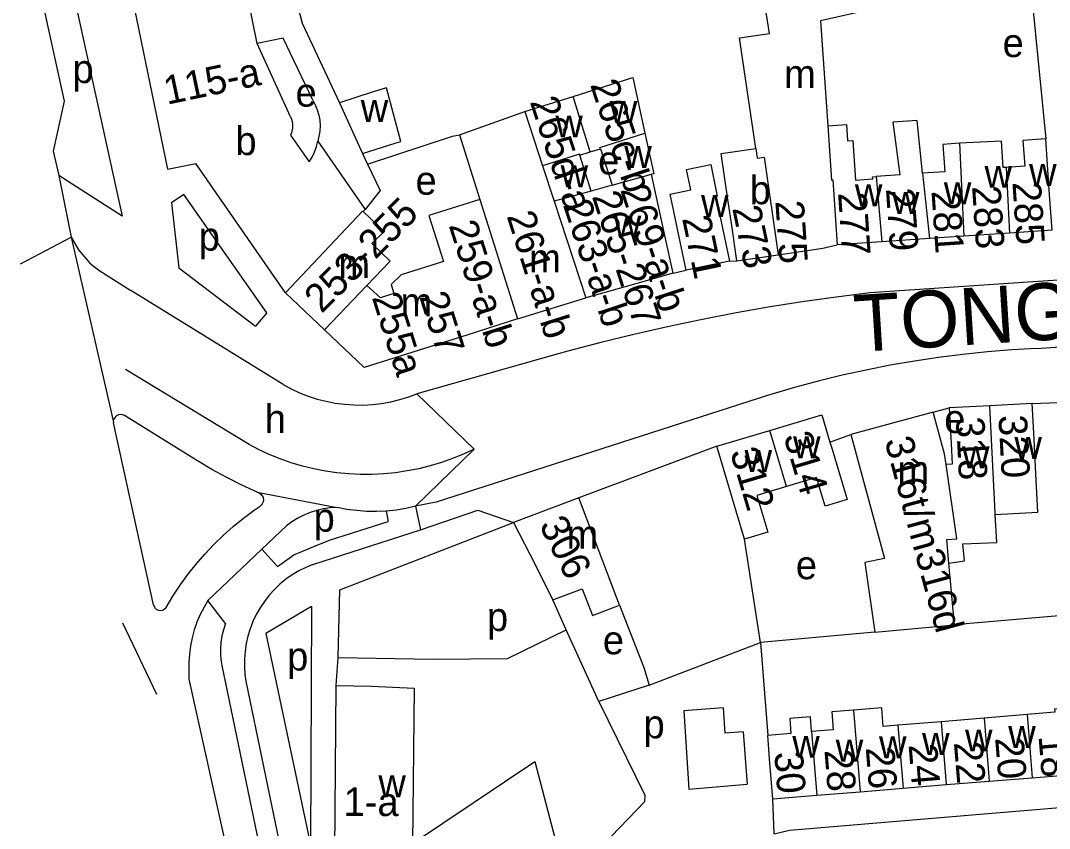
# Model space of a CAD drawing. Extents: x 163012 to 165277, y 382513 to 383987.
# Drawn here: x 163122.8 to 163267.3, y 383543.8 to 383657.3 of the extents above; entities that cross this region are included whole.
import ezdxf

# ---------------------------------------------------------------- set-up
doc = ezdxf.new("R2010")
doc.units = 0
for name, color, linetype in [('BLT_Basislijn', 7, 'Continuous'), ('BLT_Bebouwing', 7, 'Continuous'), ('BLT_Centroide', 7, 'Continuous'), ('BLT_Huisnummer', 7, 'Continuous'), ('BLT_Huisnummer_ tussenligend', 7, 'Continuous'), ('BLT_Huisnummer_reeks', 7, 'Continuous'), ('BLT_Onderverdeling_panden', 7, 'Continuous'), ('BLT_Straatnaam_hoofdweg', 7, 'Continuous'), ('BLT_Vlakafsluiter', 7, 'Continuous')]:
    doc.layers.add(name, color=color, linetype=linetype)

msp = doc.modelspace()

# ---------------------------------------------------------------- linework, layer by layer
at = {"layer": 'BLT_Basislijn'}
for p, q in [((163129.23, 383665.51), (163137.03, 383629.85)), ((163264.55, 383663.73), (163266.82, 383640.7)), ((163170.79, 383638.64), (163171.51, 383637.16)), ((163128.13, 383635.56), (163129.89, 383626.91)), ((163137.03, 383629.85), (163128.13, 383635.56)), ((163145.71, 383632.87), (163143.96, 383631.72)), ((163143.96, 383631.72), (163144.99, 383622.58)), ((163157.35, 383616.28), (163145.71, 383632.87)), ((163222.36, 383623.51), (163223.43, 383623.57)), ((163144.99, 383622.58), (163155.75, 383614.4)), ((163214.46, 383621.84), (163216.29, 383622.24)), ((163292.17, 383622.44), (163242.12, 383619.08)), ((163159.64, 383606.21), (163138.24, 383619.41)), ((163157.35, 383616.28), (163155.75, 383614.4)), ((163198.32, 383610.5), (163178.46, 383604.91)), ((163154.86, 383597.75), (163137.5, 383608.29)), ((163251.02, 383602.32), (163253.26, 383602.91)), ((163264.92, 383603.53), (163268.55, 383603.66)), ((163146.39, 383596.22), (163137.35, 383601.85)), ((163135.78, 383601.1), (163135.81, 383600.83)), ((163141.42, 383575.27), (163135.81, 383600.83)), ((163236.5, 383598.11), (163239.43, 383599.2)), ((163220.59, 383597.52), (163201.23, 383590.27)), ((163174.15, 383588.43), (163174.43, 383586.95)), ((163166.18, 383584.35), (163174.43, 383586.95)), ((163156.68, 383583.09), (163160.11, 383586.35)), ((163163.97, 383583.43), (163166.18, 383584.35)), ((163226.75, 383569.98), (163224.48, 383584.49)), ((163156.68, 383583.09), (163149.09, 383575.85)), ((163156.68, 383583.09), (163158.86, 383580.65)), ((163161.15, 383582.26), (163163.97, 383583.43)), ((163158.86, 383580.65), (163161.15, 383582.26)), ((163151.57, 383572.61), (163149.09, 383575.85)), ((163199.45, 383571.74), (163197.54, 383575.93)), ((163141.42, 383575.27), (163141.64, 383574.82)), ((163163.66, 383575.02), (163157.23, 383571.21)), ((163163.66, 383575.02), (163163.52, 383541.54)), ((163157.23, 383571.21), (163163.52, 383541.54)), ((163204.02, 383561.65), (163199.45, 383571.74)), ((163242.79, 383571.43), (163226.75, 383569.98)), ((163211.08, 383563.97), (163226.75, 383569.98)), ((163226.75, 383569.98), (163227.75, 383556.91)), ((163151.06, 383566.75), (163163.86, 383504.66)), ((163167.13, 383563.92), (163167.4, 383567.87)), ((163167.4, 383567.87), (163180.73, 383567.64)), ((163146.42, 383564.8), (163164.61, 383482.94)), ((163154.43, 383564.54), (163166.52, 383506.06)), ((163211.08, 383563.97), (163204.02, 383561.65)), ((163221.5, 383560.78), (163215.98, 383560.35)), ((163215.98, 383560.35), (163216.67, 383549.34)), ((163221.5, 383560.78), (163221.74, 383557.21)), ((163224.3, 383557.4), (163221.74, 383557.21)), ((163224.3, 383557.4), (163224.86, 383550.06)), ((163216.67, 383549.34), (163224.86, 383550.06)), ((163228.67, 383543.09), (163228.47, 383548.01))]:
    msp.add_line(p, q, dxfattribs=at)
for points in [[(163158.9, 383670.1), (163162.32, 383656.97), (163167.56, 383645.78)], [(163125.83, 383659.87), (163128.9, 383646.02), (163127.35, 383638.96), (163128.13, 383635.56)], [(163163.83, 383646.16), (163159.67, 383654.83), (163156.02, 383654.11)], [(163163.83, 383646.16), (163164.18, 383645.49), (163164.46, 383644.78), (163164.67, 383644.05), (163164.8, 383643.31), (163164.84, 383642.55), (163164.81, 383641.8), (163164.52, 383640.38)], [(163171.51, 383637.16), (163183.46, 383641.09), (163184.43, 383641.26)], [(163171.51, 383637.16), (163173.3, 383633.43), (163171.18, 383630.79)], [(163129.89, 383626.91), (163130.89, 383625.13), (163132.47, 383623.24), (163133.75, 383622.24), (163138.24, 383619.41)], [(163242.12, 383619.08), (163237.35, 383618.49), (163232.58, 383617.81), (163227.83, 383617.05), (163223.09, 383616.22), (163218.37, 383615.3), (163213.66, 383614.31), (163208.96, 383613.24), (163204.29, 383612.09), (163199.64, 383610.87), (163198.32, 383610.5)], [(163265.52, 383611.25), (163289.56, 383612.93), (163314.73, 383614.61), (163334.86, 383616.1)], [(163265.52, 383611.25), (163262.07, 383611.06), (163258.63, 383610.79), (163255.19, 383610.43), (163251.77, 383610), (163248.36, 383609.49), (163244.95, 383608.9), (163241.57, 383608.23), (163238.2, 383607.49), (163234.85, 383606.66), (163231.51, 383605.76), (163228.2, 383604.78), (163227.88, 383604.68)], [(163159.64, 383606.21), (163160.79, 383605.59), (163161.97, 383605.04), (163163.19, 383604.56), (163164.43, 383604.16), (163165.7, 383603.84), (163166.98, 383603.59), (163168.28, 383603.42), (163169.58, 383603.33), (163170.89, 383603.32), (163172.2, 383603.4), (163173.49, 383603.55), (163174.78, 383603.78), (163176.05, 383604.09), (163177.3, 383604.47), (163178.46, 383604.91)], [(163227.88, 383604.68), (163181.17, 383589.65), (163178.24, 383589.1)], [(163137.35, 383601.85), (163137.08, 383601.95), (163136.8, 383601.98), (163136.51, 383601.93), (163136.26, 383601.81), (163136.04, 383601.62), (163135.89, 383601.38), (163135.78, 383601.1)], [(163186.48, 383597.13), (163184.98, 383596.43), (163183.46, 383595.8), (163181.9, 383595.25), (163180.32, 383594.77), (163178.71, 383594.37), (163177.1, 383594.05), (163175.46, 383593.8), (163173.82, 383593.64), (163172.17, 383593.56), (163170.52, 383593.55), (163168.87, 383593.63), (163167.22, 383593.79), (163165.59, 383594.02), (163163.96, 383594.34), (163162.36, 383594.73), (163160.78, 383595.2), (163159.22, 383595.74), (163157.69, 383596.36), (163156.19, 383597.06), (163154.86, 383597.75)], [(163156, 383591.06), (163153.85, 383592.05), (163151.73, 383593.12), (163149.65, 383594.25), (163147.61, 383595.46), (163146.39, 383596.22)], [(163156, 383591.06), (163156.28, 383590.97), (163156.52, 383590.8), (163156.71, 383590.58), (163156.83, 383590.31), (163156.88, 383590.02), (163156.84, 383589.73), (163156.73, 383589.46), (163156.55, 383589.23), (163156.43, 383589.13)], [(163143.2, 383574.87), (163144.16, 383576.46), (163145.18, 383578.01), (163146.28, 383579.51), (163147.43, 383580.97), (163148.65, 383582.37), (163149.93, 383583.72), (163151.26, 383585.02), (163152.65, 383586.25), (163154.09, 383587.42), (163155.58, 383588.53), (163156.43, 383589.13)], [(163167.25, 383588.92), (163166.28, 383588.86), (163165.33, 383588.73), (163164.39, 383588.52), (163163.46, 383588.23), (163162.57, 383587.86), (163161.71, 383587.43), (163160.88, 383586.92), (163160.11, 383586.35)], [(163174.15, 383588.43), (163172.76, 383588.37), (163171.38, 383588.38), (163170, 383588.48), (163168.63, 383588.66), (163167.25, 383588.92)], [(163178.24, 383589.1), (163176.89, 383588.8), (163175.52, 383588.57), (163174.15, 383588.43)], [(163178.97, 383585.8), (163187.03, 383588.55), (163192.05, 383586.81)], [(163163.85, 383580.93), (163178.97, 383585.8)], [(163167.4, 383567.87), (163167.62, 383577.37), (163192.05, 383586.81)], [(163163.85, 383580.93), (163162.85, 383580.51), (163161.88, 383580.02), (163160.94, 383579.47), (163160.05, 383578.84), (163159.21, 383578.15), (163158.42, 383577.4), (163157.69, 383576.6), (163157.02, 383575.74), (163156.42, 383574.84), (163155.88, 383573.89), (163155.41, 383572.91), (163155.02, 383571.9), (163154.7, 383570.86), (163154.46, 383569.8), (163154.3, 383568.72), (163154.22, 383567.64), (163154.22, 383566.55), (163154.29, 383565.47), (163154.43, 383564.54)], [(163149.09, 383575.85), (163148.54, 383574.93), (163148.01, 383573.9), (163147.55, 383572.83), (163147.17, 383571.74), (163146.86, 383570.62), (163146.63, 383569.48), (163146.48, 383568.33), (163146.41, 383567.17), (163146.42, 383566), (163146.42, 383564.8)], [(163288, 383575.41), (163286.58, 383575.27), (163254.01, 383572.46)], [(163141.64, 383574.82), (163141.88, 383574.6), (163142.14, 383574.49), (163142.42, 383574.46), (163142.7, 383574.5), (163142.95, 383574.63), (163143.2, 383574.87)], [(163206.91, 383575.19), (163210.36, 383566.43), (163211.08, 383563.97)], [(163151.57, 383572.61), (163151.27, 383571.76), (163151.05, 383570.88), (163150.91, 383569.98), (163150.85, 383569.08), (163150.87, 383568.17), (163150.97, 383567.27), (163151.06, 383566.75)], [(163180.73, 383567.64), (163191.18, 383567.7), (163199.45, 383571.74)], [(163204.02, 383561.65), (163210.5, 383548.52), (163210.43, 383547.56), (163205.81, 383542.75)], [(163228.67, 383543.09), (163230.79, 383543.58), (163300.04, 383549.39), (163313.3, 383550.28)]]:
    msp.add_lwpolyline(points, dxfattribs=at)
at = {"layer": 'BLT_Bebouwing'}
for p, q in [((163156.02, 383654.11), (163153.08, 383668.35)), ((163160.68, 383643.78), (163156.02, 383654.11)), ((163193.63, 383644.53), (163200.4, 383646.67)), ((163167.56, 383645.78), (163170.79, 383638.64)), ((163184.43, 383641.26), (163193.63, 383644.53)), ((163164.52, 383640.38), (163171.18, 383630.79)), ((163184.43, 383641.26), (163187.29, 383632.2)), ((163260.62, 383640.39), (163254.7, 383640.08)), ((163170.79, 383638.64), (163175.56, 383640.15)), ((163202.78, 383638.88), (163204.24, 383639.32)), ((163204.24, 383639.32), (163205.88, 383634.19)), ((163201.33, 383638.43), (163202.78, 383638.88)), ((163202.95, 383633.38), (163201.33, 383638.43)), ((163205.88, 383634.19), (163202.95, 383633.38)), ((163170.9, 383630.49), (163171.18, 383630.79)), ((163261.75, 383627.46), (163255.32, 383627.02)), ((163267.7, 383627.86), (163261.75, 383627.46)), ((163243.78, 383626.24), (163237.51, 383625.81)), ((163250.49, 383626.69), (163243.78, 383626.24)), ((163255.32, 383627.02), (163250.49, 383626.69)), ((163222.36, 383623.51), (163216.29, 383622.24)), ((163223.43, 383623.57), (163229.24, 383624.43)), ((163214.46, 383621.84), (163207.74, 383619.94)), ((163165.49, 383613.87), (163159.99, 383619.1)), ((163192.6, 383615.41), (163202.2, 383618.38)), ((163192.6, 383615.41), (163185.46, 383613.15)), ((163171.05, 383608.59), (163165.49, 383613.87)), ((163185.46, 383613.15), (163171.05, 383608.59)), ((163258.95, 383603.22), (163253.26, 383602.91)), ((163264.92, 383603.53), (163258.95, 383603.22)), ((163251.02, 383602.32), (163239.43, 383599.2)), ((163220.59, 383597.52), (163228.06, 383599.75)), ((163224.48, 383584.49), (163220.59, 383597.52)), ((163201.23, 383590.27), (163192.05, 383586.81)), ((163206.91, 383575.19), (163201.23, 383590.27)), ((163254.01, 383572.46), (163253.21, 383581.09)), ((163242.79, 383571.43), (163254.01, 383572.46)), ((163166.83, 383531.75), (163167.13, 383563.92)), ((163258.88, 383550.48), (163264.93, 383550.97)), ((163264.93, 383550.97), (163270.98, 383551.46)), ((163240.72, 383549), (163246.77, 383549.5)), ((163246.77, 383549.5), (163252.82, 383549.99)), ((163252.82, 383549.99), (163258.88, 383550.48)), ((163228.47, 383548.01), (163234.67, 383548.51)), ((163234.67, 383548.51), (163240.72, 383549))]:
    msp.add_line(p, q, dxfattribs=at)
for points in [[(163226.06, 383639.36), (163223.77, 383654.9), (163227.99, 383655.52), (163225.77, 383669.73), (163231.9, 383670.64)], [(163153.08, 383668.35), (163137.52, 383665.12), (163143.42, 383636.43)], [(163254.39, 383661.65), (163235.18, 383657.29), (163236.21, 383642.55)], [(163200.4, 383646.67), (163208.79, 383649.33), (163210.5, 383641.5)], [(163175.56, 383640.15), (163176.21, 383640.35), (163174.18, 383647.88), (163172.33, 383647.29), (163167.56, 383645.78)], [(163160.68, 383643.78), (163160.81, 383643.49), (163160.91, 383643.16), (163160.96, 383642.81), (163160.98, 383642.5), (163160.97, 383642.2), (163160.9, 383641.81), (163160.82, 383641.54), (163160.68, 383641.21)], [(163249.52, 383635.87), (163248.74, 383643.3), (163245.33, 383643.07), (163246.33, 383635.63), (163243, 383635.41)], [(163236.21, 383642.55), (163238.81, 383642.73), (163238.96, 383640.44), (163239.73, 383640.49), (163240.11, 383634.9), (163242.52, 383635.07), (163242.49, 383635.37), (163243, 383635.41)], [(163160.68, 383641.21), (163163.3, 383637.49), (163163.72, 383638.15), (163164.07, 383638.86), (163164.34, 383639.65), (163164.52, 383640.38)], [(163210.5, 383641.5), (163211.74, 383635.81), (163211.44, 383635.73)], [(163261.27, 383636.69), (163260.82, 383636.66), (163260.62, 383640.39)], [(163266.82, 383640.7), (163263.61, 383640.49), (163263.86, 383636.87), (163261.27, 383636.69)], [(163267.7, 383627.86), (163267.36, 383632.85), (163267.08, 383637.04), (163266.82, 383640.7)], [(163223.43, 383623.57), (163222.69, 383628.52), (163222.15, 383632.17), (163221.2, 383638.64), (163226.06, 383639.36)], [(163254.7, 383640.08), (163252.38, 383639.92), (163252.64, 383636.08), (163249.52, 383635.87)], [(163143.42, 383636.43), (163147.4, 383637.25)], [(163159.99, 383619.1), (163147.4, 383637.25)], [(163216.29, 383622.24), (163215.27, 383627.14), (163214.38, 383631.37), (163214.06, 383632.93), (163216.96, 383633.53), (163216.36, 383636.4), (163219.74, 383637.11), (163220.67, 383632.64), (163220.47, 383632.6), (163221.34, 383628.4), (163222.36, 383623.51)], [(163214.46, 383621.84), (163213.4, 383626.73), (163211.44, 383635.73)], [(163187.29, 383632.2), (163180.15, 383629.95), (163182.19, 383623.48)], [(163170.9, 383630.49), (163173.87, 383627.69), (163172.11, 383626.03), (163174.72, 383623.54), (163171.44, 383620.1)], [(163229.24, 383624.43), (163235.48, 383625.36), (163237.51, 383625.81)], [(163182.19, 383623.48), (163176.23, 383621.59), (163174.83, 383620.23), (163175.23, 383618.97), (163173.32, 383618.36), (163171.44, 383620.1)], [(163207.74, 383619.94), (163202.2, 383618.38)], [(163253.26, 383602.91), (163253.53, 383597.92), (163253.68, 383594.99), (163252.82, 383594.94)], [(163259.73, 383587.94), (163265.73, 383588.26), (163265.44, 383593.63), (163265.18, 383598.52), (163264.92, 383603.53)], [(163228.06, 383599.75), (163235.36, 383601.93), (163236.5, 383598.11)], [(163252.82, 383594.94), (163252.6, 383596.45), (163251.02, 383602.32)], [(163239.43, 383599.2), (163240.74, 383594.37), (163244.15, 383581.76), (163241.42, 383581.22), (163242.79, 383571.43)], [(163236.5, 383598.11), (163236.79, 383597.14), (163238.9, 383590.05), (163235.81, 383589.12), (163234.61, 383593.12), (163230.41, 383591.87)], [(163230.41, 383591.87), (163226.21, 383590.62), (163227.75, 383585.47), (163224.48, 383584.49)], [(163253.21, 383581.09), (163255.41, 383581.41), (163255.16, 383583.8), (163259.93, 383584.02), (163259.73, 383587.94)], [(163192.05, 383586.81), (163194.3, 383582.35), (163197.54, 383575.93)], [(163197.54, 383575.93), (163201.7, 383577.5), (163203.11, 383573.75), (163206.91, 383575.19)], [(163167.13, 383563.92), (163172.06, 383563.83), (163178.09, 383563.53), (163177.84, 383541.73), (163195.03, 383553.22), (163198.13, 383541.46), (163182.99, 383539.4), (163182.24, 383537.23), (163186.27, 383535.98), (163183.55, 383526.84), (163166.83, 383531.75)], [(163233.89, 383557.45), (163233.78, 383559.52), (163230.84, 383559.28), (163231.01, 383557.17), (163227.75, 383556.91)], [(163239.79, 383560.46), (163236.77, 383560.21), (163236.97, 383557.7), (163233.89, 383557.45)], [(163246.05, 383558.35), (163243.98, 383558.18), (163243.77, 383560.78), (163239.79, 383560.46)], [(163264.21, 383559.84), (163258.16, 383559.32)], [(163270.25, 383560.38), (163270.01, 383560.36), (163269.98, 383560.76), (163268.06, 383560.61), (163268.1, 383560.15), (163264.21, 383559.84)], [(163252.11, 383558.81), (163246.05, 383558.35)], [(163258.16, 383559.32), (163252.11, 383558.81)], [(163228.47, 383548.01), (163228.07, 383552.99), (163227.75, 383556.91)]]:
    msp.add_lwpolyline(points, dxfattribs=at)
at = {"layer": 'BLT_Onderverdeling_panden'}
for p, q in [((163202.78, 383638.88), (163200.4, 383646.67)), ((163193.63, 383644.53), (163196.12, 383636.93)), ((163254.7, 383640.08), (163255.32, 383627.02)), ((163196.12, 383636.93), (163197.76, 383631.95)), ((163205.88, 383634.19), (163211.44, 383635.73)), ((163243, 383635.41), (163243.78, 383626.24)), ((163249.52, 383635.87), (163250.49, 383626.69)), ((163202.95, 383633.38), (163197.76, 383631.95)), ((163187.29, 383632.2), (163192.6, 383615.41)), ((163197.76, 383631.95), (163202.2, 383618.38)), ((163171.44, 383620.1), (163165.49, 383613.87)), ((163230.41, 383591.87), (163228.06, 383599.75)), ((163239.79, 383560.46), (163240.72, 383549)), ((163264.21, 383559.84), (163264.93, 383550.97)), ((163246.05, 383558.35), (163246.77, 383549.5)), ((163252.11, 383558.81), (163252.82, 383549.99)), ((163258.16, 383559.32), (163258.88, 383550.48)), ((163233.89, 383557.45), (163234.67, 383548.51))]:
    msp.add_line(p, q, dxfattribs=at)
for points in [[(163236.21, 383642.55), (163236.73, 383634.9), (163236.89, 383634.94), (163237.51, 383625.81)], [(163204.24, 383639.32), (163204.18, 383639.49), (163210.5, 383641.5)], [(163226.06, 383639.36), (163226.26, 383638), (163227.23, 383638.14)], [(163201.33, 383638.43), (163201.28, 383638.57), (163196.12, 383636.93)], [(163227.23, 383638.14), (163229.24, 383624.43)], [(163261.27, 383636.69), (163261.75, 383627.46)], [(163159.99, 383619.1), (163170.81, 383630.57), (163170.9, 383630.49)], [(163259.73, 383587.94), (163259.72, 383588.17), (163258.95, 383603.22)], [(163253.21, 383581.09), (163252.91, 383584.44), (163254.34, 383584.52), (163252.82, 383594.94)]]:
    msp.add_lwpolyline(points, dxfattribs=at)
at = {"layer": 'BLT_Vlakafsluiter'}
for p, q in [((163122.76, 383623.17), (163129.89, 383626.91)), ((163129.89, 383626.91), (163135.78, 383601.1)), ((163178.46, 383604.91), (163186.48, 383597.13)), ((163186.48, 383597.13), (163178.24, 383589.1)), ((163156, 383591.06), (163167.25, 383588.92)), ((163178.24, 383589.1), (163178.97, 383585.8)), ((163141.91, 383562.65), (163137.12, 383572.66))]:
    msp.add_line(p, q, dxfattribs=at)

# ---------------------------------------------------------------- texts
at = {"layer": 'BLT_Centroide'}
for s, p in [('e', (163260.76, 383652.19)), ('p', (163130.05, 383648.55)), ('m', (163230.05, 383647.84)), ('e', (163161.4, 383645.23)), ('w', (163170.56, 383643.08)), ('w', (163205.56, 383642.93)), ('w', (163197.91, 383640.91)), ('b', (163152.95, 383638.43)), ('w', (163207.6, 383636.63)), ('e', (163203.92, 383635.71)), ('w', (163198.65, 383633.91)), ('w', (163258.22, 383633.83)), ('w', (163264.48, 383634.09)), ('e', (163178.26, 383632.86)), ('b', (163225.22, 383631.53)), ('w', (163252.5, 383631.52)), ('w', (163240, 383631.23)), ('w', (163245.21, 383630.17)), ('w', (163218.38, 383629.75)), ('w', (163206.12, 383626.86)), ('p', (163147.79, 383625.01)), ('m', (163194.23, 383621.95)), ('m', (163167.41, 383621.16)), ('m', (163176.16, 383615.78)), ('h', (163157.08, 383599.4)), ('e', (163252.56, 383599.39)), ('w', (163231.31, 383595.84)), ('w', (163262.42, 383595.75)), ('w', (163224.5, 383593.92)), ('w', (163255.06, 383594.44)), ('m', (163245.99, 383592.21)), ('p', (163163.94, 383585.53)), ('m', (163199.48, 383583.14)), ('e', (163231.7, 383578.85)), ('p', (163188.3, 383571.57)), ('e', (163204.58, 383568.3)), ('p', (163160.22, 383566.02)), ('p', (163210.3, 383556.5)), ('w', (163261.55, 383555.14)), ('w', (163231.2, 383553.77)), ('w', (163243.39, 383553.7)), ('w', (163249.44, 383554.17)), ('w', (163255.48, 383554.66)), ('w', (163237.31, 383553.22)), ('w', (163173.04, 383548.23))]:
    msp.add_text(s, height=4, dxfattribs=at).set_placement(p)
at = {"layer": 'BLT_Huisnummer'}
for s, rotation, p in [('281', 273.8851, (163250.76, 383633.38)), ('285', 273.8883, (163262.13, 383634.61)), ('277', 273.8848, (163237.63, 383633.11)), ('273', 281.7716, (163222.75, 383630.97)), ('271', 281.7716, (163215.71, 383629.54)), ('320', 273.0489, (163260.17, 383601.85)), ('314', 286.6285, (163229.94, 383598.93)), ('312', 286.6214, (163222.43, 383596.72)), ('306', 296.7254, (163195.57, 383586.47)), ('18', 274.644, (163265.8, 383556.82)), ('26', 274.6461, (163241.52, 383555.18)), ('22', 274.6596, (163253.91, 383555.92)), ('30', 274.6559, (163228.67, 383554.51))]:
    msp.add_text(s, height=4, rotation=rotation, dxfattribs=at).set_placement(p)
at = {"layer": 'BLT_Huisnummer_ tussenligend'}
for s, rotation, p in [('279', 273.8848, (163244.36, 383633.7)), ('283', 273.8851, (163256.46, 383634.03)), ('275', 273.8872, (163228.82, 383631.96)), ('318', 273.0489, (163254.18, 383601.59)), ('20', 274.644, (163259.7, 383556.54)), ('24', 274.6596, (163247.54, 383555.59)), ('28', 274.6461, (163235.72, 383554.82))]:
    msp.add_text(s, height=4, rotation=rotation, dxfattribs=at).set_placement(p)
at = {"layer": 'BLT_Huisnummer_reeks'}
for s, rotation, p in [('115-a', 11.9016, (163143.34, 383645.49)), ('265c-b', 288.2601, (163202.76, 383648.34)), ('265d-a', 288.2601, (163194.29, 383645.93)), ('265-267', 288.039, (163203.02, 383632.65)), ('269-a-b', 288.039, (163207, 383633.57)), ('253-255', 45.2415, (163165.08, 383616.07)), ('263-a-b', 288.2601, (163198.95, 383631.46)), ('261-a-b', 287.5488, (163191.04, 383629.89)), ('259-a-b', 287.5488, (163182.9, 383628.57)), ('255a', 287.5488, (163172.1, 383618.45)), ('257', 287.5482, (163178.76, 383618.56)), ('316t/m316d', 285.0842, (163244.14, 383598.33)), ('1-a', 359.7119, (163168.15, 383545.61))]:
    msp.add_text(s, height=4, rotation=rotation, dxfattribs=at).set_placement(p)
at = {"layer": 'BLT_Straatnaam_hoofdweg'}
msp.add_text('TONGELRESESTRAAT', height=8, rotation=3.617, dxfattribs=at).set_placement((163240.1, 383610.75))

doc.saveas('drawing.dxf')
